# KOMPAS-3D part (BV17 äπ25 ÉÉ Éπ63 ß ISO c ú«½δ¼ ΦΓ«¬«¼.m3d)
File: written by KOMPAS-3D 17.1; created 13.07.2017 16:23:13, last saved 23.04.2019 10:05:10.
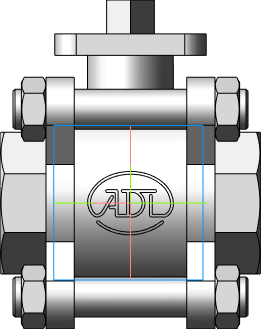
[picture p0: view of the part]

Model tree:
1. Операция без истории:2  (labels: Сталь 20  ГОСТ 1050-88)

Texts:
  DISO1
  DISO2
  BV17 Ду8 1/4" Ру63 с ISO
  BV17 Ду8 СС Ру63 с ISO
  BV17 Ду10 3/8" Ру63 с ISO
  BV17 Ду10 СС Ру63 с ISO
  BV17 Ду15 1/2" Ру63 с ISO
  BV17 Ду15 СС Ру63 с ISO
  BV17 Ду15 ФФ Ру40 с ISO
  BV17 Ду20 3/4" Ру63 с ISO
  BV17 Ду20 СС Ру40 с ISO
  BV17 Ду20 ФФ Ру40 с ISO
  BV17 Ду25 1" Ру63 с ISO
  BV17 Ду25 СС Ру63 с ISO
  BV17 Ду25 ФФ Ру40 с ISO
  BV17 Ду32 1 1/4" Ру63 с ISO
  BV17 Ду32 СС Ру63 с ISO
  BV17 Ду32 ФФ Ру40 с ISO
  BV17 Ду40 1 1/2" Ру63 с ISO
  BV17 Ду40 СС Ру63 с ISO
  BV17 Ду40 ФФ Ру40 с ISO
  BV17 Ду50 2" Ру63 с ISO
  BV17 Ду50 СС Ру63 с ISO
  BV17 Ду50 ФФ Ру40 с ISO
  BV17 Ду65 2 1/2" Ру40 с ISO
  BV17 Ду65 СС Ру40 с ISO
  BV17 Ду65 ФФ Ру40 с ISO
  BV17 Ду80 3" Ру40 с ISO
  BV17 Ду80 СС Ру40 с ISO
  BV17 Ду80 ФФ Ру40 с ISO
  BV17 Ду100 4" Ру40 с ISO
  BV17 Ду100 СС Ру40 с ISO
  BV17 Ду100 ФФ Ру40 с ISO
